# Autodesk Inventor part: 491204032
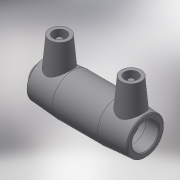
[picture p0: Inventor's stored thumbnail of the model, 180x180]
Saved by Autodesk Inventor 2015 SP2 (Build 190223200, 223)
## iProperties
Created: 2017-06
Part Number: 491204032
Material: Generic
Description: PLASSON END CAP 32
Document SubType Name: Modeling
Designer: KIM
Mass: 38.9236 g
Surface Area: 152.394 cm^2
Volume: 38.9236 cm^3
Density: 1 g/cm^3
Appearance: Default
Author: KIM
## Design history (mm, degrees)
derived "491204.ipt"
feature "Solid1::491204.ipt"
tag "TaggingFeature1"
body "Solid1"
other parameters: "d0" = 88, "d1" = 32, "d2" = 44, "d3" = 42, "d4" = 25.75, "d5" = 39.6, "d6" = 30.4, "d7" = 32, "d8" = 168 deg, "d10" = 16.8, "d11" = 5.6, "d13" = 82.4, "d14" = 17.6296, "d15" = 42, "d16" = 42, "d17" = 30.4, "d18" = 32, "d19" = 3.52592, "d20" = 168 deg, "d22" = 41.36, "d23" = 44, "d24" = 40.1192, "d25" = 135 deg, "d26" = 37.08, "d27" = 135 deg, "d29" = 42, "d30" = 15, "d31" = 32.96, "d34" = 5 deg, "d35" = 15, "d39" = 5 deg, "d41" = 4, "d42" = 14, "d43" = 0, "d45" = 4, "d46" = 14, "d47" = 0, "d48" = 103, "d49" = 1, "d51" = 25.6, "d52" = 1.854, "d53" = 35.2, "d54" = 1.854, "d56" = 3.2, "d57" = 0.96, "d60" = 15.45, "d61" = 0.64, "d63" = 103, "d64" = 1, "d66" = 25.6, "d67" = 6.4, "d68" = 35.2, "d69" = 2.06, "d70" = 0, "d71" = 1.854, "d72" = 3, "d73" = 0, "d74" = 12.18, "d75" = 4.06, "d76" = 3, "d77" = 0, "d_" = 32, "L_" = 103, "L_1" = 42, "D_" = 44, "A_" = 42, "d_2" = 12, "L_0" = 88, "d55" = 3.2
